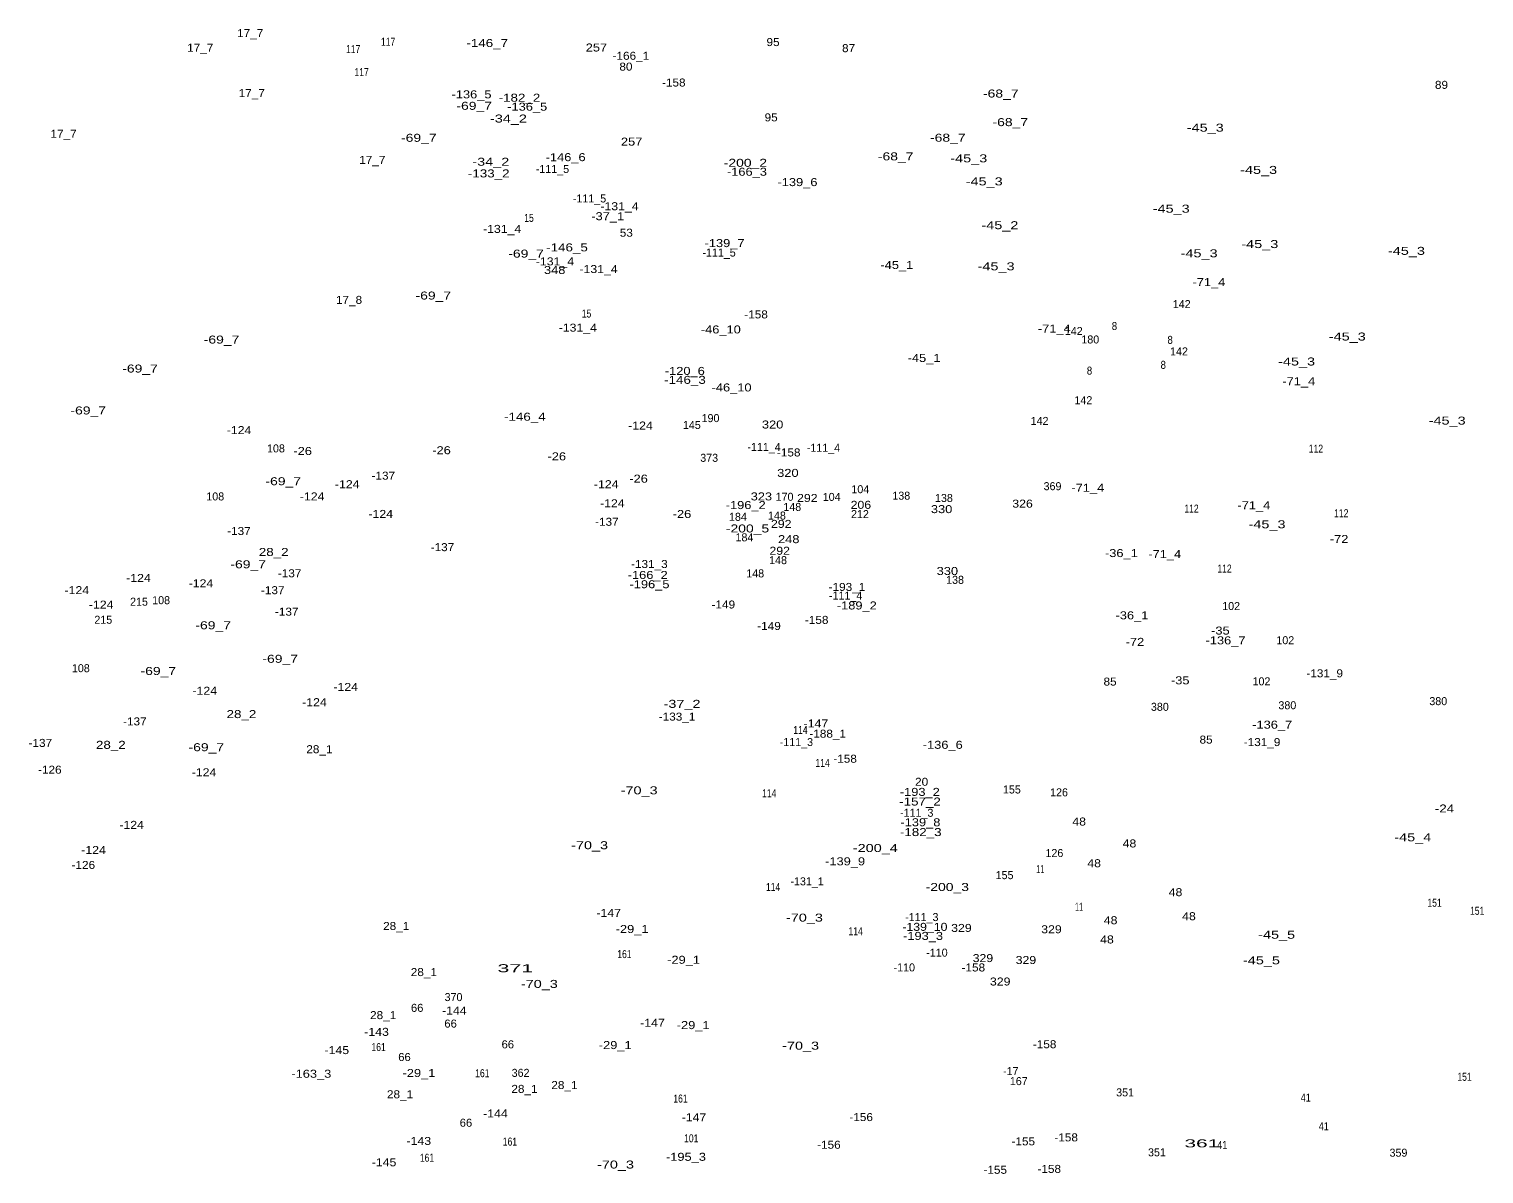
# Model space of a CAD drawing. Extents: x -662996 to -659766, y -998554 to -993949.
# Drawn here: x -661497 to -660770, y -997415 to -996842 of the extents above; entities that cross this region are included whole.
import ezdxf
from ezdxf.enums import TextEntityAlignment as Align

# ---------------------------------------------------------------- set-up
doc = ezdxf.new("R2010")
doc.units = 0
doc.header["$LTSCALE"] = 1.6
doc.layers.add('24', color=7, linetype='Continuous')

msp = doc.modelspace()

# ---------------------------------------------------------------- texts
at = {"layer": '24'}
for s, width, p in [('17_7', 1.1, (-661386.93, -996846.42)), ('117', 0.8, (-661317.981, -996850.77)), ('-146_7', 1.25, (-661268.431, -996851.38)), ('95', 1.1, (-661125.54, -996850.9)), ('17_7', 1.1, (-661411.89, -996853.72)), ('117', 0.8, (-661335.451, -996854.42)), ('257', 1.2, (-661213.85, -996853.62)), ('-166_1', 1.1, (-661196.62, -996857.76)), ('87', 1.1, (-661087.78, -996853.95)), ('117', 0.8, (-661331.231, -996865.94)), ('80', 1.1, (-661199.09, -996863.17)), ('-158', 1.1, (-661175.171, -996871.13)), ('89', 1.1, (-660791.38, -996872.29)), ('17_7', 1.1, (-661386.16, -996876.39)), ('-136_5', 1.2, (-661276.28, -996877.04)), ('-182_2', 1.25, (-661252.319, -996878.72)), ('-68_7', 1.3, (-661011.701, -996876.63)), ('-69_7', 1.3, (-661274.949, -996882.77)), ('-136_5', 1.2, (-661248.441, -996883.19)), ('95', 1.1, (-661126.5, -996888.55)), ('-34_2', 1.35, (-661257.82, -996889.13)), ('-68_7', 1.3, (-661006.941, -996890.92)), ('-45_3', 1.35, (-660909.47, -996893.68)), ('17_7', 1.1, (-661480.24, -996896.75)), ('-69_7', 1.3, (-661302.63, -996898.76)), ('257', 1.2, (-661196.23, -996900.66)), ('-68_7', 1.3, (-661038.171, -996898.71)), ('17_7', 1.1, (-661325.87, -996909.81)), ('-34_2', 1.35, (-661266.65, -996910.73)), ('-146_6', 1.2, (-661229.24, -996908.44)), ('-68_7', 1.3, (-661064.25, -996908.05)), ('-45_3', 1.35, (-661027.69, -996909.03)), ('-133_2', 1.25, (-661267.689, -996916.56)), ('-200_2', 1.3, (-661139.37, -996911.26)), ('-166_3', 1.2, (-661138.6, -996915.72)), ('-45_3', 1.35, (-660882.78, -996914.81)), ('-139_6', 1.2, (-661113.33, -996920.9)), ('-45_3', 1.35, (-661020, -996920.55)), ('15', 0.8, (-661247.559, -996938.78)), ('-37_1', 1.2, (-661208.2, -996937.95)), ('-131_4', 1.15, (-661202.309, -996932.96)), ('-45_3', 1.35, (-660926.5, -996934.19)), ('-131_4', 1.15, (-661260.98, -996944.3)), ('53', 1.1, (-661198.9, -996946.2)), ('-45_2', 1.35, (-661012.13, -996942.45)), ('-146_5', 1.25, (-661228.55, -996953.54)), ('-139_7', 1.2, (-661149.79, -996951.39)), ('-45_3', 1.35, (-660882.2, -996951.88)), ('-69_7', 1.3, (-661249.02, -996956.65)), ('-131_4', 1.15, (-661234.579, -996960.53)), ('-45_3', 1.35, (-660912.54, -996956.49)), ('-45_3', 1.35, (-660808.89, -996955.27)), ('348', 1.2, (-661234.72, -996964.83)), ('-131_4', 1.15, (-661212.78, -996964.37)), ('-45_1', 1.2, (-661063.669, -996962.33)), ('-45_3', 1.35, (-661014.05, -996963)), ('-71_4', 1.2, (-660907.64, -996970.89)), ('17_8', 1.1, (-661337.52, -996979.78)), ('-69_7', 1.3, (-661295.4, -996977.61)), ('15', 0.8, (-661218.76, -996986.61)), ('-158', 1.1, (-661134.03, -996987.04)), ('-131_4', 1.15, (-661223.15, -996993.66)), ('-46_10', 1.2, (-661151.65, -996994.55)), ('-71_4', 1.2, (-660984.95, -996994.13)), ('8', 0.9, (-660954.86, -996992.84)), ('-69_7', 1.3, (-661401.26, -996999.62)), ('8', 0.9, (-660927.02, -996999.76)), ('-45_3', 1.35, (-660838.46, -996998.1)), ('-45_1', 1.2, (-661050.04, -997008.81)), ('8', 0.9, (-660930.47, -997012.24)), ('-45_3', 1.35, (-660863.81, -997010.58)), ('-69_7', 1.3, (-661442.01, -997014.1)), ('-146_3', 1.25, (-661169.58, -997019.75)), ('-120_6', 1.2, (-661169.65, -997015.29)), ('8', 0.9, (-660967.34, -997015.12)), ('-46_10', 1.2, (-661146.28, -997023.55)), ('-71_4', 1.2, (-660862.71, -997020.42)), ('-69_7', 1.3, (-661467.91, -997035.05)), ('-146_4', 1.25, (-661249.63, -997038.18)), ('-45_3', 1.35, (-660788.54, -997040.12)), ('-124', 1.15, (-661392.5, -997044.88)), ('-124', 1.15, (-661191.81, -997042.59)), ('320', 1.2, (-661125.75, -997042.08)), ('-26', 1.2, (-661360.7, -997055.31)), ('-26', 1.2, (-661291.27, -997054.93)), ('-158', 1.1, (-661117.711, -997056.04)), ('112', 0.8, (-660854.14, -997054.15)), ('-26', 1.2, (-661233.67, -997058)), ('-69_7', 1.3, (-661370.419, -997070.43)), ('-137', 1.1, (-661320.38, -997067.65)), ('-26', 1.2, (-661192.77, -997069.14)), ('320', 1.2, (-661118.13, -997066.27)), ('-124', 1.15, (-661355.95, -997078.02)), ('-124', 1.15, (-661338.43, -997071.92)), ('-124', 1.15, (-661208.95, -997071.92)), ('323', 1.2, (-661131.38, -997078.02)), ('-71_4', 1.2, (-660968.19, -997073.69)), ('-124', 1.15, (-661205.9, -997081.45)), ('-196_2', 1.2, (-661139.21, -997082.34)), ('292', 1.15, (-661108.41, -997078.81)), ('206', 1.15, (-661081.63, -997082.23)), ('330', 1.2, (-661041.28, -997084.37)), ('326', 1.15, (-661000.81, -997081.63)), ('112', 0.8, (-660916.35, -997084.11)), ('-71_4', 1.2, (-660885.18, -997082.45)), ('-124', 1.15, (-661321.67, -997086.78)), ('-137', 1.1, (-661208.63, -997090.7)), ('-26', 1.2, (-661171.07, -997086.81)), ('292', 1.15, (-661121.46, -997091.76)), ('-45_3', 1.35, (-660878.59, -997091.96)), ('112', 0.8, (-660841.47, -997086.42)), ('-137', 1.1, (-661392.57, -997095.31)), ('-200_5', 1.3, (-661138.309, -997094.04)), ('248', 1.2, (-661117.699, -997099.38)), ('-72', 1.2, (-660842.571, -997099.3)), ('28_2', 1.25, (-661375.19, -997105.78)), ('-137', 1.1, (-661290.81, -997103.38)), ('292', 1.15, (-661122.22, -997105.19)), ('-36_1', 1.2, (-660951.4, -997106.34)), ('-71_4', 1.2, (-660929.73, -997106.83)), ('-69_7', 1.3, (-661387.939, -997111.95)), ('-131_3', 1.1, (-661187.39, -997111.81)), ('112', 0.8, (-660899.84, -997114.08)), ('-124', 1.15, (-661442.77, -997118.78)), ('-124', 1.15, (-661411.55, -997121.45)), ('-137', 1.1, (-661367.23, -997116.44)), ('-166_2', 1.2, (-661188.21, -997117.28)), ('330', 1.2, (-661038.4, -997115.3)), ('-124', 1.15, (-661473.62, -997124.88)), ('-137', 1.1, (-661375.67, -997124.89)), ('-196_5', 1.2, (-661187.31, -997121.91)), ('-193_1', 1.1, (-661088.591, -997123.27)), ('-124', 1.15, (-661461.43, -997132.11)), ('-137', 1.1, (-661368.68, -997135.62)), ('-149', 1.1, (-661150.4, -997132.04)), ('-189_2', 1.2, (-661083.671, -997132.53)), ('-69_7', 1.3, (-661405.449, -997142.43)), ('-149', 1.1, (-661127.551, -997142.79)), ('-158', 1.1, (-661103.731, -997139.75)), ('-36_1', 1.2, (-660946.12, -997137.46)), ('-72', 1.2, (-660944.63, -997150.73)), ('-136_7', 1.2, (-660899.34, -997149.97)), ('-35', 1.2, (-660901.91, -997145.08)), ('-69_7', 1.3, (-661432.87, -997165.28)), ('-69_7', 1.3, (-661371.939, -997159.19)), ('85', 1.1, (-660957.059, -997170.58)), ('-35', 1.2, (-660921.98, -997169.95)), ('-131_9', 1.1, (-660849.77, -997166.44)), ('-124', 1.15, (-661409.64, -997175.16)), ('-124', 1.15, (-661339.19, -997173.26)), ('28_2', 1.25, (-661391.31, -997186.83)), ('-124', 1.15, (-661354.8, -997180.88)), ('-37_2', 1.35, (-661171.05, -997181.71)), ('-137', 1.1, (-661444.6, -997190.49)), ('-133_1', 1.1, (-661173.53, -997188.09)), ('-147', 1.15, (-661104.111, -997191.51)), ('-136_7', 1.2, (-660876.01, -997192.11)), ('-137', 1.1, (-661491.84, -997201.24)), ('114', 0.8, (-661111.84, -997194.76)), ('-188_1', 1.1, (-661098.23, -997196.63)), ('85', 1.1, (-660909.059, -997199.58)), ('-131_9', 1.1, (-660881.071, -997200.82)), ('28_2', 1.25, (-661456.6, -997202.2)), ('-69_7', 1.3, (-661408.88, -997203.38)), ('28_1', 1.1, (-661352.34, -997204.38)), ('-136_6', 1.2, (-661040.7, -997202.18)), ('-126', 1.1, (-661487.11, -997214.62)), ('-124', 1.15, (-661410.02, -997215.92)), ('114', 0.8, (-661100.76, -997211.23)), ('-158', 1.1, (-661089.53, -997209.15)), ('20', 1.1, (-661051.26, -997220.66)), ('-70_3', 1.35, (-661192.49, -997224.95)), ('114', 0.8, (-661127.449, -997226.4)), ('-157_2', 1.25, (-661052.08, -997230.54)), ('-193_2', 1.2, (-661052.16, -997225.72)), ('-24', 1.25, (-660789.86, -997234.02)), ('-124', 1.15, (-661446.2, -997242.21)), ('-139_8', 1.2, (-661051.87, -997240.9)), ('48', 1.15, (-660972.52, -997240.54)), ('-70_3', 1.35, (-661217.25, -997252.38)), ('-182_3', 1.25, (-661051.709, -997245.81)), ('48', 1.15, (-660947.37, -997251.49)), ('-45_4', 1.35, (-660805.73, -997248.42)), ('-124', 1.15, (-661465.24, -997254.78)), ('-200_4', 1.35, (-661074.41, -997253.78)), ('-126', 1.1, (-661470.35, -997262.24)), ('-139_9', 1.2, (-661089.52, -997260.44)), ('11', 0.55, (-660991.94, -997264.3)), ('48', 1.15, (-660965.03, -997261.38)), ('114', 0.8, (-661125.53, -997273.27)), ('-200_3', 1.3, (-661038.429, -997273.26)), ('48', 1.15, (-660924.34, -997275.85)), ('151', 0.8, (-660794.84, -997281.13)), ('-147', 1.15, (-661207.701, -997286.22)), ('-70_3', 1.35, (-661109.86, -997288.57)), ('11', 0.55, (-660972.55, -997283.13)), ('48', 1.15, (-660917.61, -997287.86)), ('151', 0.8, (-660773.53, -997285.16)), ('28_1', 1.1, (-661313.94, -997292.74)), ('-29_1', 1.2, (-661196.01, -997294.27)), ('114', 0.8, (-661084.25, -997295.36)), ('-139_10', 1.15, (-661049.64, -997293.18)), ('329', 1.15, (-661031.38, -997293.72)), ('329', 1.15, (-660986.35, -997294.39)), ('48', 1.15, (-660956.78, -997289.87)), ('-193_3', 1.2, (-661050.561, -997297.71)), ('48', 1.15, (-660958.61, -997299.48)), ('-45_5', 1.35, (-660873.79, -997297.13)), ('161', 0.8, (-661199.851, -997306.79)), ('-29_1', 1.2, (-661170.28, -997309.64)), ('329', 1.15, (-661020.62, -997308.8)), ('329', 1.15, (-660999.12, -997309.76)), ('-45_5', 1.35, (-660881.37, -997309.91)), ('28_1', 1.1, (-661300.11, -997315.79)), ('371', 2, (-661254.403, -997313.87)), ('-158', 1.1, (-661025.41, -997313.49)), ('-70_3', 1.35, (-661242.38, -997321.71)), ('329', 1.15, (-661011.98, -997320.51)), ('28_1', 1.1, (-661320.46, -997337.3)), ('66', 1.05, (-661303.46, -997333.67)), ('-144', 1.15, (-661284.88, -997335.01)), ('-143', 1.15, (-661323.75, -997345.67)), ('66', 1.05, (-661286.76, -997341.54)), ('-147', 1.15, (-661185.811, -997341.15)), ('-29_1', 1.2, (-661165.481, -997342.29)), ('161', 0.8, (-661322.74, -997353.27)), ('66', 1.05, (-661258.15, -997351.92)), ('-29_1', 1.2, (-661204.451, -997352.28)), ('-70_3', 1.35, (-661111.76, -997352.57)), ('-158', 1.1, (-660989.78, -997351.85)), ('-145', 1.15, (-661343.63, -997354.79)), ('66', 1.05, (-661309.8, -997358.25)), ('-163_3', 1.2, (-661356.37, -997366.61)), ('-29_1', 1.2, (-661302.571, -997366.25)), ('161', 0.8, (-661270.89, -997366.33)), ('151', 0.8, (-660779.86, -997368.14)), ('28_1', 1.1, (-661249.81, -997374.18)), ('28_1', 1.1, (-661229.84, -997372.26)), ('28_1', 1.1, (-661312.02, -997376.87)), ('161', 0.8, (-661171.821, -997379.01)), ('41', 0.85, (-660859.23, -997378.54)), ('-144', 1.15, (-661264.33, -997386.48)), ('-147', 1.15, (-661165.071, -997388.39)), ('-156', 1.1, (-661081.5, -997388.27)), ('66', 1.05, (-661279.08, -997391.1)), ('41', 0.85, (-660850.209, -997392.85)), ('-143', 1.15, (-661302.63, -997400.21)), ('161', 0.8, (-661257.071, -997400.52)), ('101', 0.8, (-661166.44, -997398.88)), ('-156', 1.1, (-661097.63, -997402.1)), ('-155', 1.1, (-661000.451, -997400.41)), ('-158', 1.1, (-660979.02, -997398.43)), ('361', 1.95, (-660911.173, -997401.41)), ('41', 0.85, (-660900.99, -997402.27)), ('-145', 1.15, (-661320.01, -997410.88)), ('161', 0.8, (-661298.541, -997408.59)), ('-70_3', 1.35, (-661204.3, -997412)), ('-195_3', 1.2, (-661169.091, -997408.13)), ('-155', 1.1, (-661014.471, -997414.62)), ('-158', 1.1, (-660987.471, -997414.18))]:
    msp.add_text(s, height=4, dxfattribs=dict(at, width=width)).set_placement(p, align=Align.CENTER)
for s, p in [('-111_5', (-661235.83, -996914.36)), ('-111_5', (-661217.3, -996929.08)), ('-111_5', (-661152.53, -996956.11)), ('142', (-660921.26, -996981.89)), ('142', (-660975.209, -996995.34)), ('180', (-660966.95, -996999.56)), ('142', (-660922.6, -997005.52)), ('142', (-660970.41, -997029.91)), ('190', (-661156.801, -997038.88)), ('142', (-660992.299, -997040.28)), ('145', (-661166.15, -997042.31)), ('108', (-661374.06, -997054.02)), ('-111_4', (-661130.059, -997053.32)), ('-111_4', (-661100.329, -997053.71)), ('373', (-661157.483, -997058.72)), ('108', (-661404.4, -997078.03)), ('104', (-661081.919, -997074.43)), ('138', (-661061.439, -997077.65)), ('369', (-660985.828, -997072.91)), ('170', (-661119.791, -997078.2)), ('148', (-661115.929, -997083.27)), ('104', (-661096.24, -997078.27)), ('138', (-661040.12, -997078.8)), ('184', (-661143.1, -997088.21)), ('148', (-661123.61, -997087.59)), ('212', (-661082.11, -997086.85)), ('184', (-661139.84, -997098.49)), ('148', (-661123.04, -997109.87)), ('148', (-661134.459, -997116.5)), ('138', (-661034.559, -997119.71)), ('-111_4', (-661089.25, -997127.58)), ('215', (-661442.52, -997130.65)), ('108', (-661431.47, -997129.89)), ('102', (-660896.54, -997132.82)), ('215', (-661460.37, -997139.67)), ('102', (-660869.46, -997149.91)), ('108', (-661471.6, -997163.89)), ('102', (-660881.37, -997170.46)), ('380', (-660932.171, -997183.19)), ('380', (-660868.431, -997182.41)), ('380', (-660792.981, -997180.36)), ('-111_3', (-661113.89, -997200.81)), ('155', (-661006.16, -997224.51)), ('126', (-660982.581, -997225.94)), ('-111_3', (-661053.72, -997236.16)), ('126', (-660984.89, -997256.29)), ('-131_1', (-661108.53, -997270.43)), ('155', (-661009.809, -997267.34)), ('-111_3', (-661051.17, -997288.29)), ('-110', (-661043.611, -997306.07)), ('-110', (-661059.931, -997313.46)), ('370', (-661285.287, -997328.29)), ('362', (-661251.753, -997366.16)), ('-17', (-661006.7, -997365.29)), ('167', (-661002.7, -997370.3)), ('351', (-660949.549, -997375.93)), ('351', (-660933.62, -997405.89)), ('359', (-660812.883, -997406.08))]:
    msp.add_text(s, height=4, dxfattribs=at).set_placement(p, align=Align.CENTER)

doc.saveas('drawing.dxf')
